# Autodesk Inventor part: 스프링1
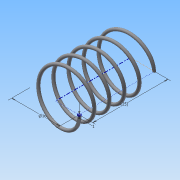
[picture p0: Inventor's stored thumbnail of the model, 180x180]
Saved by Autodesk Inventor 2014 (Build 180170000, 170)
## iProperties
Created: 2015-06
Part Number: 스프링1
Material: 강철, 연강
Document SubType Name: Modeling
Designer: Administrator
Density: 7.86 g/cm^3
Appearance: 강철
Mass: 1.53535 g
Surface Area: 7.89042 cm^2
Volume: 0.195337 cm^3
Author: Administrator
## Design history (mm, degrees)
sketch "스케치1"
  geometry: L1 (0, 0)-(8, 0); L2 (8, 0)-(8, 21.5); L3 (8, 21.5)-(0, 21.5); L4 (0, 21.5)-(0, 0); C1 r 0.5 at (8, 0)
  constraints: 8 end point, 2 parallel, 1 centre point, 1 coincident, 1 horizontal, 1 perpendicular
  dimensions: "d0" = 16 diameter of L2 L4; "d1" = 21.5 distance of L1.end L2.end (derived); "d2" = 1 diameter of C1
feature "코일1" sketch "스케치1" pitch "d3" = 10; turns "d5" = 5; dims "d4" = 21.5 (= d1), "d6" = 0, angle "d7" = 90 deg, angle "d8" = 90 deg, "d9" = 0, "d10" = 0
sketch "스케치2"
  geometry: L1 (-8.5, 0)-(-7.5, 0) reference; 1 further point
  constraints: 1 horizontal alignment
extrude "돌출1" cut sketch "스케치2" stored distance "d11" = 10; taper "d12" = 0 deg
node "작업 평면1"
sketch "스케치3"
  geometry: L1 (8.5, 0)-(7.5, 0) reference; 1 further point
  constraints: 1 horizontal alignment
extrude "돌출2" cut sketch "스케치3" stored distance "d14" = 10; taper "d15" = 0 deg
node "솔리드1"
node "절단 모서리 투영1"
node "절단 모서리 투영2"
other parameters: "d13" = -21.5 (= -d1)
